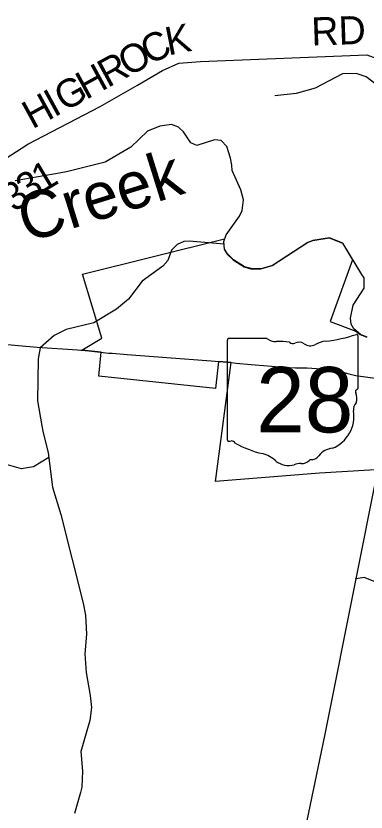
# Model space of a CAD drawing. Extents: x 1525783 to 1900577, y 218250 to 627376.
# Drawn here: x 1664681 to 1668410, y 487300 to 495778 of the extents above; entities that cross this region are included whole.
import ezdxf

# ---------------------------------------------------------------- set-up
doc = ezdxf.new("R2010")
doc.units = 0
for name, color, linetype in [('GM_X_Corporation', 7, 'Continuous'), ('GM_X_Minor_River', 7, 'Continuous'), ('GM_X_Minor_River_Text', 7, 'Continuous'), ('GM_X_State_Location', 7, 'Continuous'), ('GM_X_State_Route', 7, 'Continuous'), ('GM_X_State_Shield', 7, 'Continuous'), ('GM_X_Township_Road', 7, 'Continuous'), ('GM_X_Township_Road_Text', 7, 'Continuous'), ('GM_X_US_Route', 7, 'Continuous')]:
    doc.layers.add(name, color=color, linetype=linetype)

msp = doc.modelspace()

# ---------------------------------------------------------------- linework, layer by layer
at = {"layer": 'GM_X_Corporation'}
msp.add_lwpolyline([(1669522.5, 491003.6), (1667915.1, 490910.5), (1666805.2, 490821.1), (1666972, 492086.8), (1666836.8, 492098.7), (1666806.4, 491810.3), (1665563.3, 491940.9), (1665590.2, 492197), (1665381.1, 492217.5), (1665596.8, 492345.9), (1665388.8, 493028), (1666902.4, 493405.2), (1666891.3, 493373.5), (1666900, 493293.1), (1666929.4, 493242.5), (1666994.7, 493179.3), (1667112, 493105.3), (1667182, 493086.2), (1667288.5, 493084.6), (1667409.6, 493120.9), (1667785, 493363.9), (1667841.6, 493387.1), (1668016.8, 493414.5), (1668160.5, 493358.1), (1668267.2, 493180.5), (1668027.8, 492522.7), (1668302.7, 492422.6), (1668346.1, 492384.3), (1668420, 492357.1)], dxfattribs=at)
at = {"layer": 'GM_X_Minor_River'}
for points in [[(1669755.2, 494503.9), (1669695.3, 494569.5), (1669537.9, 494654.2), (1669226.4, 494640.9), (1669076.7, 494705.4), (1668808.1, 494868), (1668686.4, 494920), (1668410.5, 495128.8), (1668304.6, 495166.6), (1668159.9, 495160.7), (1667868.2, 495008.7), (1667664.5, 494953.6), (1667439.1, 494927)], [(1668365.3, 493023.8), (1668163.8, 493359.1), (1668020.1, 493415.5), (1667844.9, 493388.1), (1667788.3, 493364.9), (1667412.9, 493121.8), (1667291.8, 493085.6), (1667185.4, 493087.2), (1667115.4, 493106.3), (1666998, 493180.3), (1666932.7, 493243.5), (1666903.4, 493294.1), (1666894.6, 493374.5), (1666919.8, 493446.3), (1667063.5, 493644.8), (1667090.6, 493704.5), (1667104.4, 493818.7), (1667078, 493925.4), (1666984.8, 494133.5), (1666979.6, 494189.7), (1666966.7, 494262.1), (1666928.5, 494389.1), (1666865.2, 494450.3), (1666795, 494459.4), (1666607.3, 494400), (1666543.4, 494425.1), (1666464.9, 494542.6), (1666411.5, 494593.6), (1666337.6, 494622.8), (1666212.8, 494604.7), (1666083.4, 494550.5), (1665906, 494380.7), (1665632.3, 494220.3), (1665218.9, 494118.3), (1665162.5, 494107.1), (1664671.1, 494022.4)], [(1666897.6, 493347.3), (1666527.1, 493378.1), (1666468.8, 493375), (1666398, 493344), (1666338.8, 493284.7), (1666298.9, 493173), (1666245.7, 493111.6), (1666026.3, 492952.4), (1665880.7, 492762.1), (1665752.5, 492655.7), (1665509.2, 492511), (1665214.7, 492437.2), (1665089.2, 492375), (1664940.5, 492242.8), (1664918.6, 492124.8), (1664911.6, 491677.5), (1664957.7, 491412), (1664966.8, 491357.7), (1665025.5, 491124.1), (1665072, 490758.2), (1665157.9, 490470.1), (1665396.2, 489525.5), (1665422.3, 489396.7), (1665433.3, 489196), (1665415.9, 488983.6), (1665428.8, 488784.8), (1665471.2, 488541.4), (1665485.3, 488412.8), (1665469.1, 488276.6), (1665373.6, 487945), (1665390.4, 487736.1), (1665381.7, 487565.7), (1665368.8, 487509.8), (1665303, 487286.1)], [(1668423.4, 492358.1), (1668349.5, 492385.3), (1668280.1, 492446.5), (1668250.8, 492497.1), (1668245.7, 492559.4), (1668274, 492697.4), (1668391.3, 492878.2), (1668391.7, 492988.5), (1668365.3, 493023.8)], [(1665031.7, 491074.8), (1664868.5, 490978), (1664739.6, 490955.9), (1664565.6, 491004.7), (1664497.2, 490997.8), (1664356.8, 490881.5), (1664089.9, 490512.5), (1663842.4, 490101), (1663736.3, 489996.3), (1663477.4, 489879.9), (1663340.3, 489845.9), (1663277.3, 489798.7), (1662800.5, 489107.9), (1662680.1, 488989.4), (1662574.8, 488804.4), (1662549.7, 488742.6), (1662506.4, 488669)]]:
    msp.add_lwpolyline(points, dxfattribs=at)
at = {"layer": 'GM_X_State_Route'}
for points in [[(1662312.3, 492453.6), (1662435.1, 492447.2), (1663217.7, 492390.6), (1663908.7, 492338), (1664908, 492251.4), (1665337.1, 492220.7), (1665458.7, 492211.8), (1665669.3, 492188.3), (1665705.4, 492185.4)], [(1665705.4, 492185.4), (1665864, 492173.1)], [(1665864, 492173.1), (1666289, 492140.1), (1666759.7, 492105.4), (1666972.1, 492086.8), (1667027.3, 492081.9)], [(1667027.3, 492081.9), (1667185.8, 492067.7)], [(1667185.8, 492067.7), (1667536, 492036.5), (1667658, 492029.4), (1667784.3, 492029.4), (1667931.5, 492018.6), (1668033.5, 492009.7), (1668097.5, 491996.9), (1668151.2, 491986.7), (1668227.7, 491966.8), (1668301.8, 491950.2), (1668763.5, 491886)]]:
    msp.add_lwpolyline(points, dxfattribs=at)
at = {"layer": 'GM_X_State_Shield'}
for p, q in [((1668324.7, 491816.6), (1668324.7, 492369.4)), ((1666932.5, 492325), (1666932.5, 491268.4)), ((1667353.9, 492343.2), (1666946.2, 492343.2)), ((1668324.6, 491816.8), (1668324.7, 491816.6))]:
    msp.add_line(p, q, dxfattribs=at)
for centre, radius, start, end in [((1667828.8, 493783.7), 1476.4, 275.84447, 288.90645), ((1668309.3, 492371.7), 15.5, 351.86209, 97.738), ((1666948.5, 492327.3), 16.1, 98.1301, 188.1301), ((1667451, 492465.8), 156.4, 231.61951, 271.11188), ((1667502.9, 491750), 561.6, 80.48669, 94.98827), ((1667630.4, 492332.7), 45.1, 219.79206, 297.10237), ((1667696.7, 492210.6), 93.8, 54.46668, 119.14113), ((1667817.8, 492378.1), 112.9, 233.85621, 294.82819), ((1668017.1, 492020.5), 297, 97.34618, 120.76885), ((1668321.1, 491776.1), 24, 107.94398, 210.33697), ((1668168.5, 491706.2), 144, 340.03296, 23.64957), ((1668308.2, 491814.5), 16.6, 289.60381, 7.73413), ((1668380.2, 491585.3), 104.8, 136.8065, 186.92959), ((1667911.5, 491515), 369.3, 292.30889, 8.98584), ((1666948.6, 491266.1), 16.3, 171.95839, 258.30661), ((1666951.1, 491374.2), 124.2, 267.33899, 280.60386), ((1666976.5, 491207.4), 44.8, 29.74838, 93.27175), ((1667541.8, 492156.7), 1066.1, 240.41292, 257.1985), ((1668067.2, 490971.7), 202.2, 94.40312, 142.57675), ((1667223.9, 490793.7), 333.6, 47.18416, 75.83597), ((1667811, 491166), 119.3, 282.87319, 323.27711), ((1667584.7, 491202.2), 211.7, 230.70037, 286.29184), ((1667707, 490836.8), 173.9, 85.69512, 111.20995), ((1667722.5, 491123), 112.8, 268.77702, 315.54927), ((1667824.5, 491020.7), 31.8, 65.75173, 132.64842)]:
    msp.add_arc(centre, radius, start, end, dxfattribs=at)
at = {"layer": 'GM_X_Township_Road'}
for points in [[(1663907.8, 494045.3), (1663969.5, 494023.9), (1664044.1, 494015.7), (1664110.5, 494021.2), (1664218.2, 494040.5), (1664317.7, 494076.5), (1664425.5, 494142.8), (1664516.7, 494223), (1664808.8, 494412.2), (1665578.9, 494814.6), (1665976.2, 495040.8), (1666242.4, 495195.6), (1666417.7, 495276.7), (1666646.9, 495293.3), (1668417.7, 495362.2), (1669021.3, 495143.6), (1669363.9, 495027.6)], [(1671562.3, 488047.9), (1671179.8, 487968.1), (1671014.9, 487943.1), (1670936.5, 487933.6), (1670886.2, 487923.9), (1670752, 487997), (1669091.1, 489143.5), (1668925.2, 489305.1), (1668681.7, 489571.5), (1668581.9, 489688.5), (1668505.9, 489751.2), (1668389.7, 489796.1), (1668304.9, 489782.5), (1668294.5, 489780.8)]]:
    msp.add_lwpolyline(points, dxfattribs=at)
at = {"layer": 'GM_X_US_Route'}
msp.add_lwpolyline([(1664419.7, 478176.7), (1664792.5, 478603.2), (1665058.1, 478907), (1666129.7, 480033.8), (1666213.1, 480171.3), (1666350.5, 480534.2), (1666376.5, 480648.9), (1666589.5, 481587.6), (1666605.4, 481657.7), (1667468.8, 485711.7), (1667971.1, 488113.2), (1668304.9, 489782.5), (1668526.2, 490889), (1668531.1, 490909.9)], dxfattribs=at)

# ---------------------------------------------------------------- texts
at = {"layer": 'GM_X_Minor_River_Text'}
msp.add_text('Creek', height=500.01, rotation=17.34278, dxfattribs=at).set_placement((1664795.5, 493360.1))
at = {"layer": 'GM_X_State_Location'}
for s in ['s', 'r']:
    msp.add_text(s, height=1, dxfattribs=at).set_placement((1667612.9, 491726.4))
msp.add_text('28', height=1, rotation=0.00001, dxfattribs=at).set_placement((1667361.1, 491653.7))
at = {"layer": 'GM_X_State_Shield'}
msp.add_text('28', height=696.1, dxfattribs=at).set_placement((1667239.5, 491342.9))
at = {"layer": 'GM_X_Township_Road_Text'}
for s, rotation, p in [('RD', 1.97383, (1667832.2, 495461.7)), ('K', 11.24421, (1666304.3, 495356.3)), ('C', 26.80069, (1666104.7, 495252.2)), ('O', 28.59854, (1665875.1, 495127)), ('R', 28.71948, (1665659.1, 495008.7)), ('H', 28.72383, (1665427.6, 494881.8)), ('G', 28.71919, (1665196.1, 494754.9)), ('I', 28.71948, (1665088, 494695.7)), ('H', 28.72413, (1664856.5, 494568.9)), ('1', 31.16634, (1664961.9, 493889.1)), ('3', 34.15769, (1664812.5, 493787.6)), ('3', 36.17848, (1664665.6, 493680.1))]:
    msp.add_text(s, height=300, rotation=rotation, dxfattribs=at).set_placement(p)

doc.saveas('drawing.dxf')
